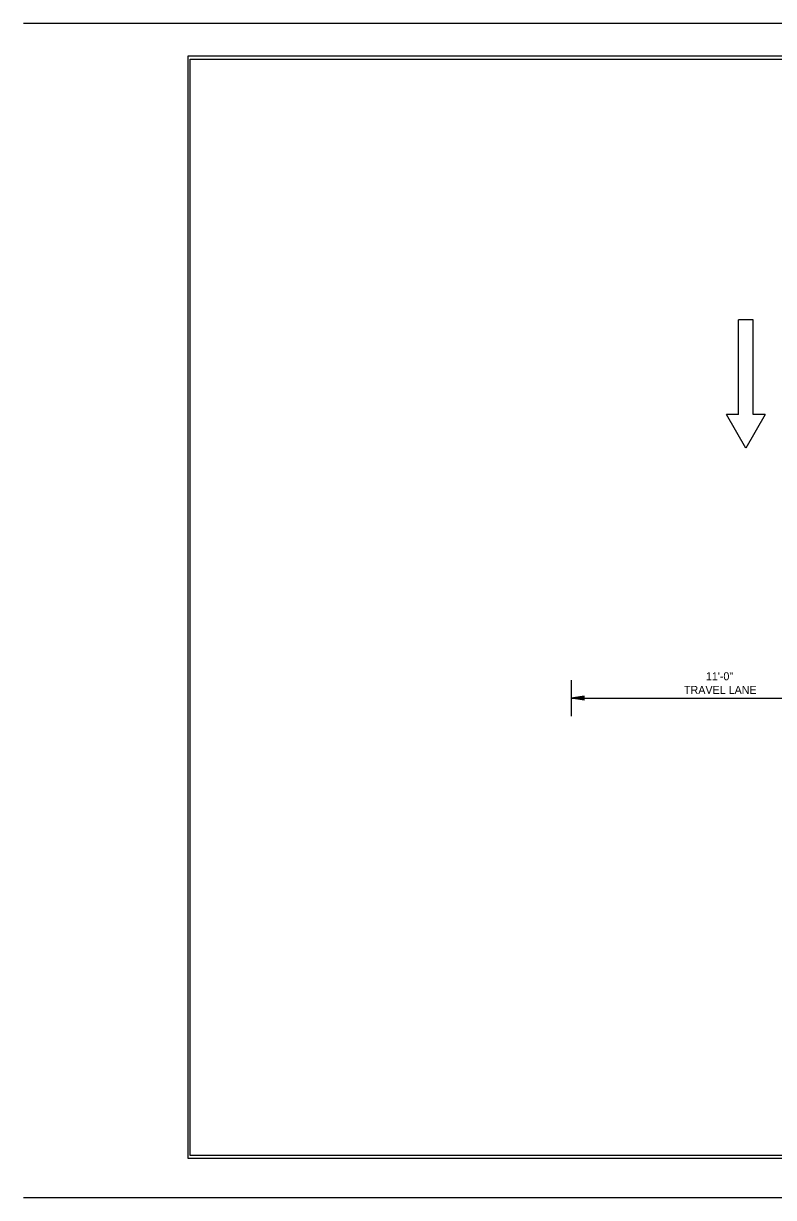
# Model space of a CAD drawing. Extents: x 714919 to 718439, y 1619644 to 1621844.
# Drawn here: x 714919 to 716325, y 1619644 to 1621844 of the extents above; entities that cross this region are included whole.
import ezdxf

# ---------------------------------------------------------------- set-up
doc = ezdxf.new("R2010")
doc.units = 0
for name, color, linetype in [('Default', 7, 'Continuous'), ('R_Border', 7, 'Continuous'), ('R_No Plot', 7, 'Continuous'), ('Roadway Special Details - R_Striping', 7, 'Continuous')]:
    doc.layers.add(name, color=color, linetype=linetype)

msp = doc.modelspace()

# ---------------------------------------------------------------- linework, layer by layer
at = {"layer": 'Default'}
for p, q in [((715945.5, 1620613.1), (715945.5, 1620545.9)), ((715969.7, 1620583.2), (715945.5, 1620579.5)), ((715969.7, 1620575.9), (715945.5, 1620579.5)), ((715947.3, 1620579.5), (717248.5, 1620579.5)), ((715969.7, 1620582.6), (715949.6, 1620579.5)), ((715969.7, 1620576.5), (715949.6, 1620579.5)), ((715969.7, 1620581.9), (715953.7, 1620579.5)), ((715969.7, 1620577.1), (715953.7, 1620579.5)), ((715969.7, 1620581.3), (715957.7, 1620579.5)), ((715969.7, 1620577.7), (715957.7, 1620579.5)), ((715969.7, 1620580.7), (715961.8, 1620579.5)), ((715969.7, 1620578.4), (715961.8, 1620579.5)), ((715969.7, 1620580.1), (715965.9, 1620579.5)), ((715969.7, 1620579), (715965.9, 1620579.5)), ((715969.7, 1620575.9), (715969.7, 1620583.2))]:
    msp.add_line(p, q, dxfattribs=at)
at = {"layer": 'R_Border'}
for p, q in [((718439, 1621843.8), (714919, 1621843.5)), ((715231.2, 1619722.5), (715231.3, 1621777.1)), ((715231.3, 1621777.1), (718393.1, 1621777.1)), ((718393.2, 1619722.5), (715231.2, 1619722.5)), ((714919.1, 1619643.5), (718439.3, 1619643.8))]:
    msp.add_line(p, q, dxfattribs=at)
at = {"layer": 'R_No Plot'}
msp.add_lwpolyline([(715227.2, 1619717.3), (718397.1, 1619717.4), (718397.2, 1621782.5), (715227.1, 1621782.3)], close=True, dxfattribs=at)
at = {"layer": 'Roadway Special Details - R_Striping'}
for p, q in [((716259, 1621110.8), (716259, 1621288.6)), ((716286.2, 1621288.6), (716259, 1621288.6)), ((716286.2, 1621110.8), (716286.2, 1621288.6)), ((716259, 1621110.8), (716236.3, 1621110.8)), ((716272.6, 1621048.1), (716236.3, 1621110.8)), ((716308.8, 1621110.8), (716272.6, 1621048.1)), ((716308.8, 1621110.8), (716286.2, 1621110.8))]:
    msp.add_line(p, q, dxfattribs=at)

# ---------------------------------------------------------------- texts
at = {"layer": 'Default'}
for s, p in [('11\'-0"', (716197.9, 1620612.9)), ('TRAVEL LANE', (716156.9, 1620587.3))]:
    msp.add_text(s, height=15, dxfattribs=at).set_placement(p)

doc.saveas('drawing.dxf')
